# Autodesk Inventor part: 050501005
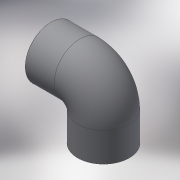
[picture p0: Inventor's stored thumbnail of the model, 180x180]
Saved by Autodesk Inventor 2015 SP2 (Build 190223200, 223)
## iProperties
Created: 2017-10
Part Number: 050501005
Material: Generic
Description: PLASSON THREADED 90° ELBOW PVC 1/2"
Document SubType Name: Modeling
Designer: KIM
Density: 1 g/cm^3
Appearance: Default
Author: KIM
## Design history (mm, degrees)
derived "050501.ipt"
feature "Solid1::050501.ipt"
tag "TaggingFeature1"
body "Solid1"
other parameters: "d7" = 0.18631, "d9" = 25, "d10" = 29.5, "d13" = 90 deg, "d19" = 90 deg, "d20" = 18.631, "d21" = 17, "d22" = 0, "d24" = 90 deg, "d26" = 16.7679, "d27" = 90 deg, "d28" = 17, "G_" = 18.631, "E_" = 25, "H_" = 42, "lt_" = 17
